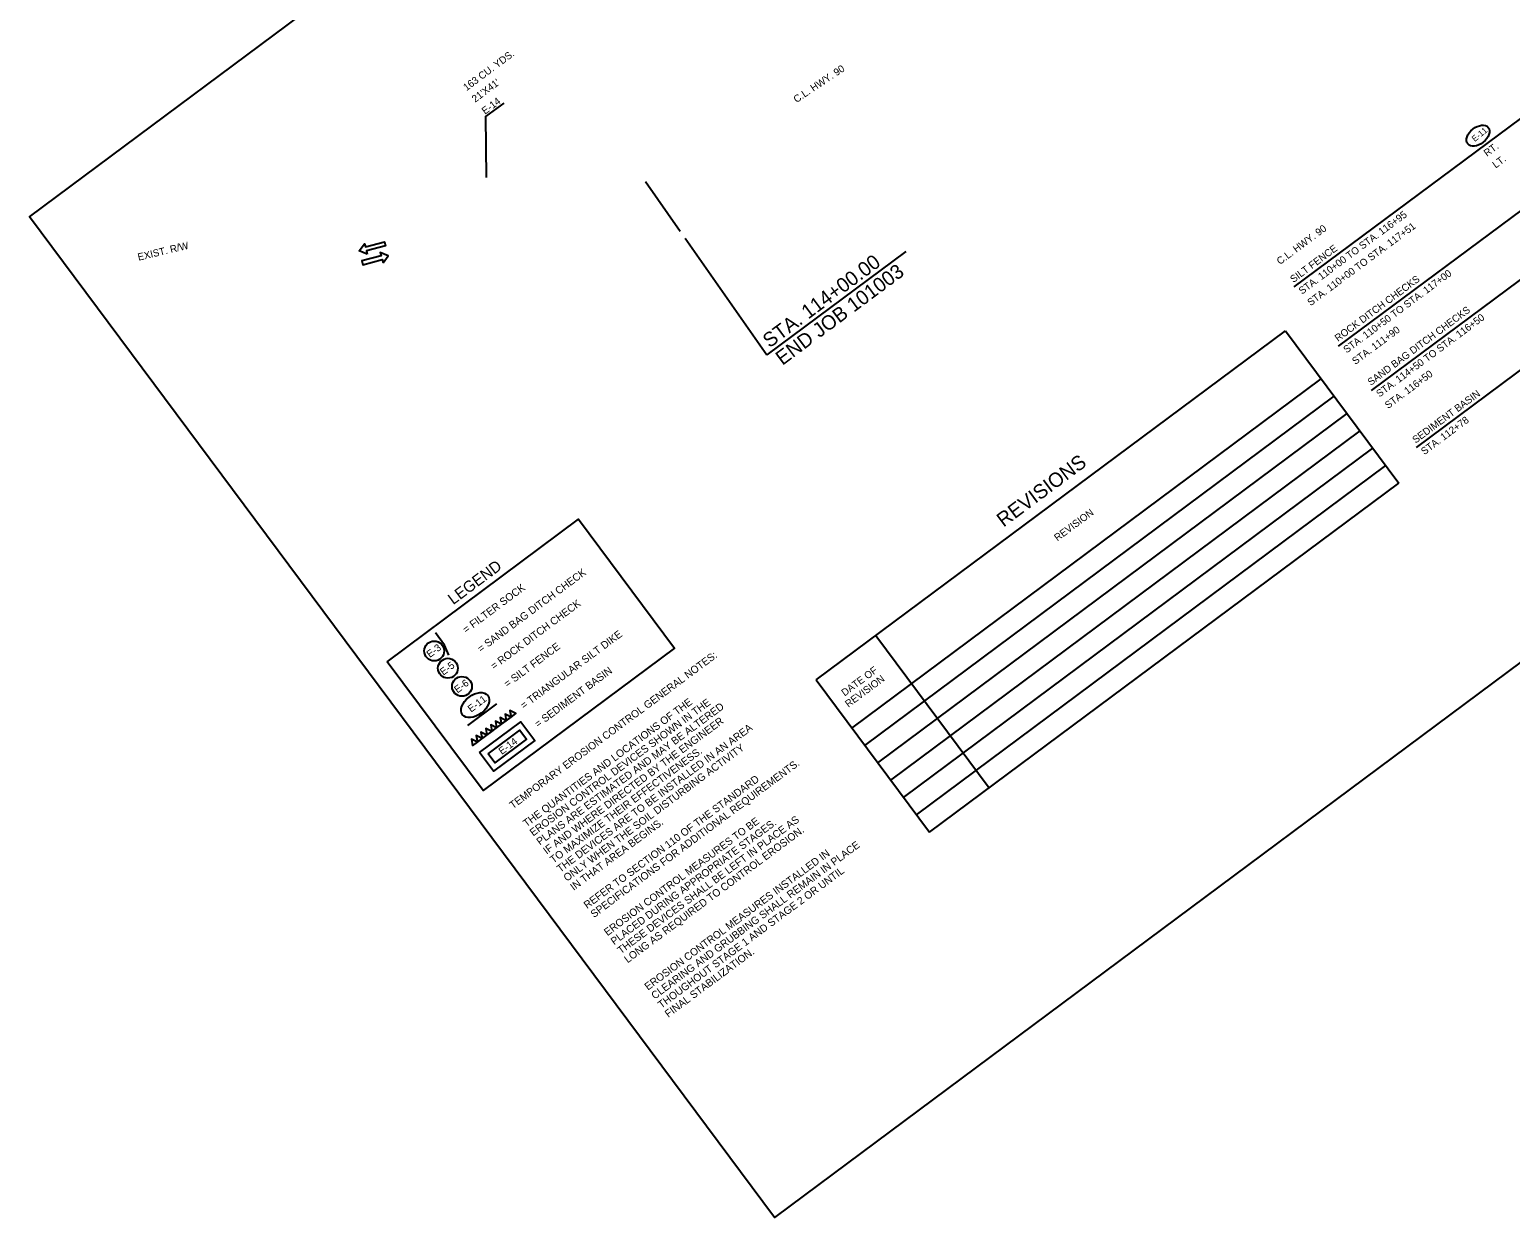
# Model space of a CAD drawing. Extents: x 1571137 to 1573037, y 731597 to 733459.
# Drawn here: x 1571137 to 1572369, y 731597 to 732586 of the extents above; entities that cross this region are included whole.
import ezdxf

# ---------------------------------------------------------------- set-up
doc = ezdxf.new("R2010")
doc.units = 0
for name, color, linetype in [('Default', 7, 'Continuous'), ('R_Annotation', 7, 'Continuous'), ('R_Contour Annot', 7, 'Continuous'), ('R_MOT', 7, 'Continuous'), ('R_No Plot', 7, 'Continuous'), ('R_Proposed Road_Lane', 7, 'Continuous'), ('R_ROW Annot', 7, 'Continuous'), ('R_TCE', 7, 'Continuous'), ('S_MSC_PT_SYM', 7, 'Continuous')]:
    doc.layers.add(name, color=color, linetype=linetype)

msp = doc.modelspace()

# ---------------------------------------------------------------- linework, layer by layer
at = {"layer": 'Default'}
msp.add_lwpolyline([(1571501.6, 732006.7), (1571525.7, 732024.7)], dxfattribs=at)
at = {"layer": 'R_Annotation'}
for p, q in [((1572189.5, 732371.9), (1572416.5, 732540.8)), ((1572226.4, 732322.4), (1572453.4, 732491.3)), ((1571649.5, 732459.7), (1571678.5, 732418.2)), ((1572253.7, 732285.7), (1572480.7, 732454.6)), ((1571682.6, 732412.3), (1571750.4, 732315.3)), ((1571866.2, 732401.4), (1571750.4, 732315.3)), ((1572291.3, 732238.2), (1572518.3, 732407.2))]:
    msp.add_line(p, q, dxfattribs=at)
msp.add_lwpolyline([(1571434.6, 732059.8), (1571593.9, 732178.4), (1571673.8, 732071.1), (1571514.4, 731952.6)], close=True, dxfattribs=at)
at = {"layer": 'R_MOT'}
for points in [[(1571418, 732399.1), (1571411.2, 732401.9), (1571415.6, 732407.8), (1571416.4, 732405.1), (1571432.4, 732409.4), (1571433.2, 732406.1), (1571417.3, 732401.8)], [(1571431.1, 732391.8), (1571435.5, 732397.7), (1571428.7, 732400.5), (1571429.5, 732397.8), (1571413.5, 732393.5), (1571414.4, 732390.2), (1571430.3, 732394.6)]]:
    msp.add_lwpolyline(points, close=True, dxfattribs=at)
at = {"layer": 'R_No Plot'}
for p, q in [((1571791.6, 732044.8), (1572182.1, 732335.4)), ((1572182.1, 732335.4), (1572276.4, 732208.6)), ((1571821.4, 732004.6), (1572212, 732295.3)), ((1571832.2, 731990.2), (1572222.7, 732280.8)), ((1571842.9, 731975.8), (1572233.5, 732266.4)), ((1571853.7, 731961.3), (1572244.2, 732252)), ((1571864.4, 731946.9), (1572254.9, 732237.5)), ((1571875.2, 731932.4), (1572265.7, 732223.1)), ((1571885.9, 731918), (1572276.4, 732208.6)), ((1571841.2, 732081.7), (1571935.5, 731954.9)), ((1571791.6, 732044.8), (1571885.9, 731918))]:
    msp.add_line(p, q, dxfattribs=at)
at = {"layer": 'R_Proposed Road_Lane'}
msp.add_lwpolyline([(1571531.6, 732524.8), (1571516.5, 732513.6), (1571516.9, 732462.8)], dxfattribs=at)
at = {"layer": 'R_TCE'}
msp.add_line((1571505.6, 731989.8), (1571541.7, 732016.7), dxfattribs=at)
for points in [[(1571485.8, 732065.3), (1571482.4, 732073.7), (1571474.9, 732083.8)], [(1571505.6, 731989.8), (1571541.7, 732016.7)]]:
    msp.add_lwpolyline(points, dxfattribs=at)
for points in [[(1571533.7, 732010.7), (1571537.7, 732013.7), (1571532.7, 732016.2)], [(1571537.7, 732013.7), (1571541.7, 732016.7), (1571536.7, 732019.2)], [(1571511.5, 731984.3), (1571545.9, 732009.9), (1571557.5, 731994.3), (1571523.1, 731968.7)], [(1571517.6, 731998.8), (1571521.6, 732001.8), (1571516.6, 732004.3)], [(1571518.5, 731983.3), (1571544.9, 732002.9), (1571550.5, 731995.4), (1571524.1, 731975.7)], [(1571521.6, 732001.8), (1571525.6, 732004.8), (1571520.7, 732007.3)], [(1571525.6, 732004.8), (1571529.7, 732007.8), (1571524.7, 732010.3)], [(1571529.7, 732007.8), (1571533.7, 732010.7), (1571528.7, 732013.3)], [(1571505.6, 731989.8), (1571509.6, 731992.8), (1571504.6, 731995.3)], [(1571509.6, 731992.8), (1571513.6, 731995.8), (1571508.6, 731998.3)], [(1571513.6, 731995.8), (1571517.6, 731998.8), (1571512.6, 732001.3)]]:
    msp.add_lwpolyline(points, close=True, dxfattribs=at)
for centre in [(1571473.7, 732068.8), (1571485.1, 732054.4), (1571496.8, 732039.3)]:
    msp.add_circle(centre, 8.26, dxfattribs=at)
for centre, major_axis in [((1572342.4, 732497.7), (8.54, 6.86)), ((1571507.8, 732023.7), (10.5, 8))]:
    msp.add_ellipse(centre, major_axis=major_axis, ratio=0.638788, dxfattribs=at)
at = {"layer": 'S_MSC_PT_SYM'}
msp.add_lwpolyline([(1572536.7, 733221.6), (1573036.7, 732549.8), (1571756.9, 731597.3), (1571137, 732430.2), (1572086.8, 733137.2), (1572116.3, 733097.5), (1572258.8, 733203.6), (1572269.5, 733189.2), (1572284.1, 733200.1), (1572282.1, 733202.7), (1572344.4, 733249.1)], dxfattribs=at)

# ---------------------------------------------------------------- texts
at = {"layer": 'Default'}
for s, height, p in [('LEGEND', 9.37, (1571489.5, 732106.9)), ('= SAND BAG DITCH CHECK', 6.25, (1571512.6, 732067.3)), ('= FILTER SOCK', 6.25, (1571500.3, 732083.2)), ('= ROCK DITCH CHECK', 6.25, (1571523.5, 732052.9)), ('= TRIANGULAR SILT DIKE', 6.25, (1571548.3, 732020.1)), ('= SILT FENCE', 6.25, (1571534.6, 732038.1)), ('= SEDIMENT BASIN', 6.25, (1571560.1, 732004.7))]:
    msp.add_text(s, height=height, rotation=36.6576, dxfattribs=at).set_placement(p)
at = {"layer": 'R_Annotation'}
for s, height, rotation, p in [('163 CU. YDS.', 6, 36.6576, (1571500.6, 732534.7)), ("21'X41'", 6, 36.6576, (1571507.8, 732525.1)), ('C.L. HWY. 90', 6, 33.804, (1571775.2, 732524.8)), ('RT.', 6, 36.6576, (1572349.9, 732480)), ('LT. ', 6, 36.6576, (1572357.1, 732470.3)), ('STA. 110+00 TO STA. 116+95', 6, 36.6576, (1572195.9, 732365.3)), ('C.L. HWY. 90', 6, 36.6576, (1572177.6, 732390)), ('STA. 110+00 TO STA. 117+51', 6, 36.6576, (1572203.1, 732355.7)), ('STA. 114+00.00', 12, 36.6576, (1571752.8, 732320.6)), ('SILT FENCE', 6, 36.6576, (1572188.8, 732375)), ('END JOB 101003', 12, 36.6576, (1571763.5, 732306.1)), ('STA. 110+50 TO STA. 117+00', 6, 36.6576, (1572233.1, 732316.4)), ('ROCK DITCH CHECKS', 6, 36.6576, (1572225.9, 732326)), ('SAND BAG DITCH CHECKS', 6, 36.6576, (1572253.2, 732289.4)), ('STA. 114+50 TO STA. 116+50', 6, 36.6576, (1572260.4, 732279.7)), ('STA. 111+90', 6, 36.6576, (1572240.3, 732306.8)), ('STA. 116+50', 6, 36.6576, (1572267.6, 732270.1)), ('SEDIMENT BASIN', 6, 36.6576, (1572290.5, 732241.3)), ('STA. 112+78', 6, 36.6576, (1572297.7, 732231.7))]:
    msp.add_text(s, height=height, rotation=rotation, dxfattribs=at).set_placement(p)
at = {"layer": 'R_Contour Annot'}
for s, p in [('TEMPORARY EROSION CONTROL GENERAL NOTES:', (1571539.2, 731937)), ('THE QUANTITIES AND LOCATIONS OF THE', (1571550.5, 731921.9)), ('EROSION CONTROL DEVICES SHOWN IN THE ', (1571556.1, 731914.3)), ('PLANS ARE ESTIMATED AND MAY BE ALTERED ', (1571561.7, 731906.8)), ('IF AND WHERE DIRECTED BY THE ENGINEER ', (1571567.3, 731899.2)), ('THE DEVICES ARE TO BE INSTALLED IN AN AREA ', (1571578.6, 731884.1)), ('ONLY WHEN THE SOIL DISTURBING ACTIVITY', (1571584.2, 731876.6)), ('TO MAXIMIZE THEIR EFFECTIVENESS. ', (1571572.9, 731891.7)), ('SPECIFICATIONS FOR ADDITIONAL REQUIREMENTS.', (1571606.7, 731846.4)), ('REFER TO SECTION 110 OF THE STANDARD ', (1571601, 731853.9)), ('EROSION CONTROL MEASURES TO BE', (1571617.9, 731831.3)), ('THESE DEVICES SHALL BE LEFT IN PLACE AS ', (1571629.1, 731816.2)), ('IN THAT AREA BEGINS.', (1571589.8, 731869)), ('PLACED DURING APPROPRIATE STAGES. ', (1571623.5, 731823.7)), ('LONG AS REQUIRED TO CONTROL EROSION.', (1571634.7, 731808.7)), ('EROSION CONTROL MEASURES INSTALLED IN ', (1571651.6, 731786)), ('CLEARING AND GRUBBING SHALL REMAIN IN PLACE ', (1571657.2, 731778.5)), ('THOUGHOUT STAGE 1 AND STAGE 2 OR UNTIL ', (1571662.8, 731770.9)), ('FINAL STABILIZATION.', (1571668.5, 731763.4))]:
    msp.add_text(s, height=6.25, rotation=36.6576, dxfattribs=at).set_placement(p)
at = {"layer": 'R_No Plot'}
for s, height, p in [('REVISIONS', 12, (1571947.5, 732171.4)), ('REVISION', 6, (1571992.4, 732159.9)), ('DATE OF', 6, (1571815.3, 732030.8)), ('REVISION', 6, (1571818.4, 732021.5))]:
    msp.add_text(s, height=height, rotation=36.6576, dxfattribs=at).set_placement(p)
at = {"layer": 'R_ROW Annot'}
msp.add_text('EXIST. R/W', height=6, rotation=13.4962, dxfattribs=at).set_placement((1571227.7, 732393.6))
at = {"layer": 'R_TCE'}
for s, height, rotation, p in [('E-14', 6, 36.6576, (1571516, 732515.1)), ('E-11', 5, 38.7878, (1572339.7, 732492.4)), ('E-3', 6, 36.6576, (1571470.1, 732062.9)), ('E-5 ', 6, 36.6576, (1571481.3, 732048.2)), ('E-6 ', 6, 36.6576, (1571493.1, 732033.4)), ('E-11', 6, 37.2648, (1571504.4, 732017.4)), ('E-14', 6, 36.6576, (1571530, 731982.2))]:
    msp.add_text(s, height=height, rotation=rotation, dxfattribs=at).set_placement(p)

doc.saveas('drawing.dxf')
